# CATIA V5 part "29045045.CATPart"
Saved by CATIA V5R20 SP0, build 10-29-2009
Part number: 29045045
Definition: NONE
Nomenclature: 29045045
Source: Unknown
Description: 29045045
Bounding box of the stored display mesh (mm): x -22.5 to 44.548, y -36.5 to 71.048, z -26.5 to 26.5
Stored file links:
  C:\Users\Utente\Desktop\IO LAVORO\3D X SITO CF\X SITO\PLASTICA\RF1\29045045.CATPart
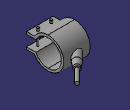
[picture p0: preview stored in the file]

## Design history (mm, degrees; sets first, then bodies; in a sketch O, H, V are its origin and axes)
Body1 "29045045" (main body)
  Solid1: solid without history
